(* Logix 5000 project; controller ControlLogix 1756-L63 rev 13.28; software revision 13.03 *)

TASK MainTask (continuous, watchdog 5000 ms) : MainProgram

MODULES
   Local : 1756-L63 (ICP 0, rev 13.28)
      Local_ENBT : 1756-ENBT (Ethernet 105.102.0.155, ICP 3, rev 1.1)
         RemoteENBT_Slot6 : 1756-ENBT (Ethernet 105.102.0.210, rev 1.1, Output RPI 20 ms)
            MNETCR : vendor 1 type 0 code 15 (ICP 1, rev 1.1, Output RPI 5 ms)
END_MODULES

TYPE MNETCRBLOCKSTATS :   // This object is used to store the block transfer statistics for the MVI56-MNETCR module.
STRUCT
   Read : INT;   // Total number of read block transfers
   Write : INT;   // Total number of write block transfers
   Parse : INT;   // Total number of blocks parsed
   Event : INT;   // Total number of event blocks received
   Cmd : INT;   // Total number of command blocks received
   Err : INT;   // Total number of block transfer errors
END_STRUCT
END_TYPE

TYPE MNETCRCLIENTSTATS :   // This object is used to store the port statistics for an MVI56-MNETCR port.
STRUCT
   CmdReq : INT;   // Total number of command list requests sent
   CmdResp : INT;   // Total number of command list responses received
   CmdErr : INT;   // Total number of command list errors
   Requests : INT;   // Total number of requests for port
   Responses : INT;   // Total number of responses for port
   ErrSent : INT;   // Total number of errors sent
   ErrRec : INT;   // Total number of errors received
   CfgErrWord : INT;   // Configuration Error Word
   CurErr : INT;   // Current Error code
   LastErr : INT;   // Last recorded error code
END_STRUCT
END_TYPE

TYPE MNETCRCMDCONTROL :   // MVI56-MNETCR Command Control
STRUCT
   ClientIDreq : INT;   // Requested Client ID.
   CmdQty : INT;   // Command Quantaty for the Client.
   CmdIndex : INT[16];   // Command Index per client. (0 to 15)
END_STRUCT
END_TYPE

TYPE MNETCRCONTROL :   // Values used by program for data transfer operation between the module and the processor.
STRUCT
   BootTimer : TIMER;   // Timer used to clear both cold and warm boot requests
   WarmBoot : BOOL;   // Partial reset of the Module.
   ColdBoot : BOOL;   // Full reset of the Module.
   EventCmdTrigger : BOOL;   // Initiates Event Command.
   EventCmdPending : BOOL;   // Allows Event Command.
   ClientID : INT;   // Client ID to poll a server with the Event Command.
   EventCmd : MNETCREVENTCMD;   // Holds Event Command configuration
   CmdControl : MNETCRCMDCONTROL;   // Holds Command Control status
   CmdControlTrigger : BOOL;   // Initiates Command Control.
   CmdControlPending : BOOL;   // Allows CmdControlTriger.
   IPAddress : MNETCRIPADDRESS;   // IP address statistics including triggers
   WriteCmdBits : INT[30];   // Selects individual clients to to activate its commands.
END_STRUCT
END_TYPE

TYPE MNETCRDATA :   // Contains Read Data (data read from the module to the processor) and Write Data (data written from the processor to the module)
STRUCT
   ReadData : INT[600];   // Data read from module
   WriteData : INT[600];   // Data to write to module
END_STRUCT
END_TYPE

TYPE MNETCREVENTCMD :   // Data structure to use for Event message generation.
STRUCT
   IP0 : INT;   // First digit of IP address
   IP1 : INT;   // Second digit of IP address
   IP2 : INT;   // Third digit of IP address
   IP3 : INT;   // Last digit of IP address
   ServPort : INT;   // TCP Service Port number (0-65535), 502 for MBAP, 2000 for MNET
   SlvAddrNode : INT;   // Modbus slave node address (0 to 247)
   DBAddress : INT;   // Module internal database to use with message
   Count : INT;   // Register or data point count
   Swap : INT;   // Swap code to use with functions 3 and 4
   MBFunction : INT;   // Modbus function code for message
   Address : INT;   // Address to interface with in device
END_STRUCT
END_TYPE

TYPE MNETCRIPADDRESS :   // This object holds IP address status with set IP & get IP triggers.
STRUCT
   IPgetTrigger : BOOL;   // Triggers get IP address.
   IPreceived : INT[4];   // Displays received IP address.
   IPsetTrigger : BOOL;   // Triggers set IP address
   IPrequested : INT[4];   // Displays requested IP address
END_STRUCT
END_TYPE

TYPE MNETCRMODULEDEF :   // This defines the whole module which includes all tags used in the program
STRUCT
   DATA : MNETCRDATA;   // Data read from module
   CONTROL : MNETCRCONTROL;   // Client ,Server Status and blocks status
   STATUS : MNETCRSTATUS;   // MNETCR Module control
   UTIL : MNETCRUTIL;   // Block statistics
END_STRUCT
END_TYPE

TYPE MNETCRSTATUS :   // This status data is returned on each read block and can be used to detect proper module operation.
STRUCT
   PassCnt : INT;   // Program cycle counter
   BlockStats : MNETCRBLOCKSTATS;   // Block Statistics
   CmdBits : INT[30];   // Client Command Status.
   ClientStatsTrigger : BOOL;   // Get Client Status
   ClientIDReq : INT;   // Client ID requested.
   ClientStatus : MNETCRCLIENTSTATS[30];   // Client Status requests
   ClientIDRec : INT;   // Client ID received.
   CmdErrorList : INT[16];   // Cmd Error List
   ClientStatsPending : BOOL;   // Allows Get Client Status
END_STRUCT
END_TYPE

TYPE MNETCRUTIL :   // Values used by program for data transfer operation between the module and the processor.
STRUCT
   LastRead : INT;   // Index of last read block
   LastWrite : INT;   // Index of last write block
   BlockIndex : INT;   // Computed block offset for data table
   ReadDataSizeGet : INT;   // Gets ReadData Array Length.
   WriteDataSizeGet : INT;   // Gets WriteData Array Length.
   ReadDataBlkCount : INT;   // Holds the value of the Block Counts of the Read Data Array.
   WriteDataBlkCount : INT;   // Holds the value of the Block Counts of the Write Data Array.
   RBTSremainder : INT;   // Holds remainder calculation value from the read array.
   WBTSremainder : INT;   // Holds remainder calculation value from the write array.
   IPgetPending : BOOL;   // Allows setting IP
   IPsetPending : BOOL;   // Allowes getting IP
END_STRUCT
END_TYPE

VAR_GLOBAL   (* controller tags *)
   MJFAULTS : DINT[12] := ([0] := 1272054862, [1] := 191551, [3] := 1256603824, [4] := 191551, [9] := 1004);
   MNETCR : MNETCRMODULEDEF;
        .INSTAT.CMDERRORLIST[0]   // Reads Command related errors
        .GETIPADDRESS   // Initiates the retreaval of IP Address from the module.
        .READIPADDRESS.IP[0]   // Reads Module's set IP Address
        .BLK3000CLIENTID   // Holds Block 3000 Client ID
        .CMDCNTRL   // Initiates Command Control
        .HALTCMDCNTRL   // Halts Command Control until the Module is ready for the next Command.
        .HALTEVENTCMD   // Halts Event Initiation until the Module is ready for the next Event.
        .SETIPADDRESS   // Initiates the setting of the IP Address for the module.
        .GETCLNTSTAT   // Initiates retreaval of Client Status.
        .HALTCLNTSTAT   // Halts Client Status Retreaval until the Module is ready for the next Status Retreaval.
        .EVENTCMD   // Initiates an Event.
        .WARMBOOT   // Re-loads MNET.CFG file
        .BLK5000CLIENTID   // Holds Block 5000 Client ID
        .BLK_1CLIENTID   // Holds Client ID for Command Bits Control.
        .HALTCMDBITCNTRL   // Halts Command Control Bits execution until the Module is ready for the next Command.
        .COLDBOOT   // Re-initializes all the module's parameters
        .BLK2000CLIENTID   // Client's Index ID.
        .BP.LASTREAD   // Index of last read block
        .BP.LASTWRITE   // Holds the value to be written on the last scan.
        .HALTSETIPADDRESS   // Halts the IP Adress Setting until the Module is ready for it.
        .HALTGETIPADDR   // Halts the IP Retreaval until the module is ready.
        .WRITEIPADDRESSACK.IP[0]   // Ack. from the module that it has received the new IP Address
END_VAR

PROGRAM MainProgram   (* routine attr 65 MainRoutine *)

ROUTINE MainRoutine   (* ladder *)
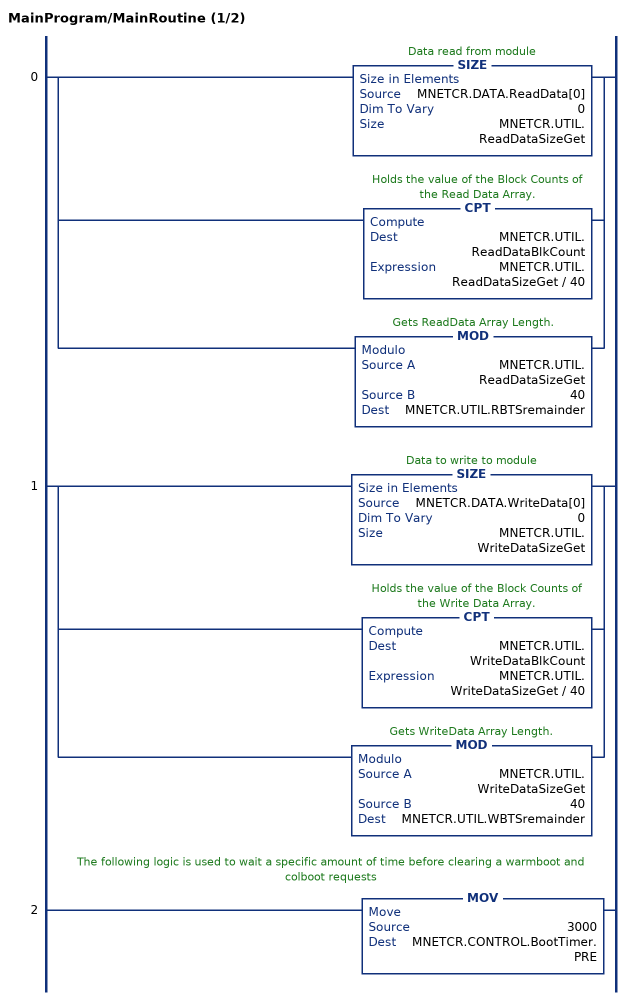
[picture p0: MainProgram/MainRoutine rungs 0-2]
   0: [SIZE(MNETCR.DATA.ReadData[0],0,MNETCR.UTIL.ReadDataSizeGet) ,CPT(MNETCR.UTIL.ReadDataBlkCount,MNETCR.UTIL.ReadDataSizeGet / 40) ,MOD(MNETCR.UTIL.ReadDataSizeGet,40,MNETCR.UTIL.RBTSremainder) ];
   1: [SIZE(MNETCR.DATA.WriteData[0],0,MNETCR.UTIL.WriteDataSizeGet) ,CPT(MNETCR.UTIL.WriteDataBlkCount,MNETCR.UTIL.WriteDataSizeGet / 40) ,MOD(MNETCR.UTIL.WriteDataSizeGet,40,MNETCR.UTIL.WBTSremainder) ];
   // The following logic is used to wait a specific amount of time before clearing a warmboot and colboot requests
   2: MOV(3000,MNETCR.CONTROL.BootTimer.PRE);
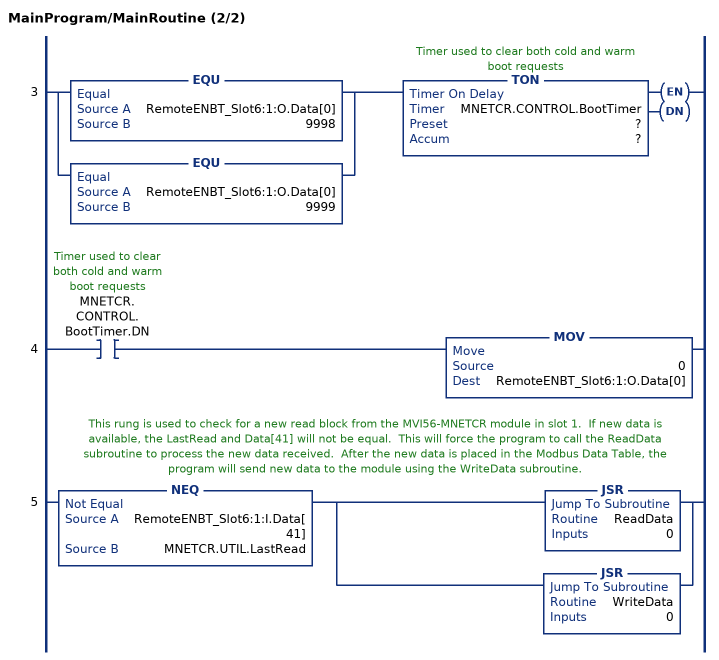
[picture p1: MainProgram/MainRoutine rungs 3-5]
   3: [EQU(RemoteENBT_Slot6:1:O.Data[0],9998) ,EQU(RemoteENBT_Slot6:1:O.Data[0],9999) ]TON(MNETCR.CONTROL.BootTimer,?,?);
   4: XIC(MNETCR.CONTROL.BootTimer.DN)MOV(0,RemoteENBT_Slot6:1:O.Data[0]);
   // This rung is used to check for a new read block from the MVI56-MNETCR module in slot 1.  If new data is available, the LastRead and Data[41] will not be equal.  This will force the program to call the ReadData subroutine to process the new data received.  After the new data is placed in the Modbus Data Table, the program will send new data to the module using the WriteData subroutine.
   5: NEQ(RemoteENBT_Slot6:1:I.Data[41],MNETCR.UTIL.LastRead)[JSR(ReadData,0) ,JSR(WriteData,0) ];
END_ROUTINE

ROUTINE ReadData   (* ladder *)
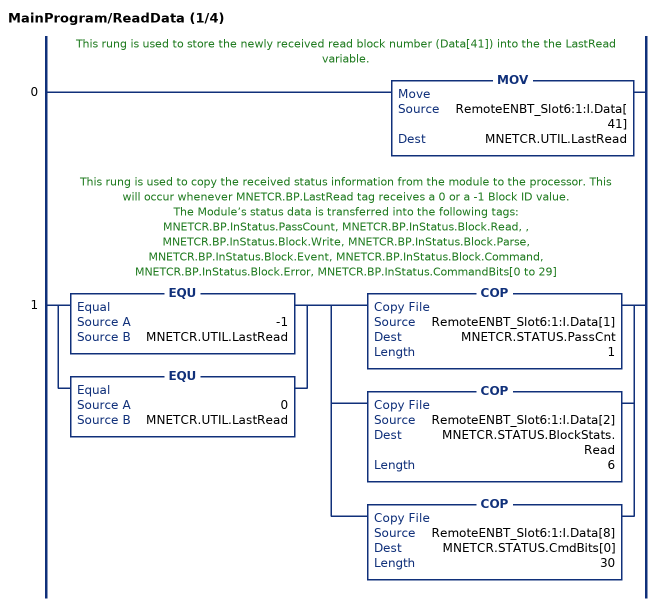
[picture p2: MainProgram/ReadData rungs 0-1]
   // This rung is used to store the newly received read block number (Data[41]) into the the LastRead variable.
   0: MOV(RemoteENBT_Slot6:1:I.Data[41],MNETCR.UTIL.LastRead);
   // This rung is used to copy the received status information from the module to the processor. This will occur whenever MNETCR.BP.LastRead tag receives a 0 or a -1 Block ID value.
   // The Module’s status data is transferred into the following tags:
   // MNETCR.BP.InStatus.PassCount, MNETCR.BP.InStatus.Block.Read, , MNETCR.BP.InStatus.Block.Write, MNETCR.BP.InStatus.Block.Parse, MNETCR.BP.InStatus.Block.Event, MNETCR.BP.InStatus.Block.Command, MNETCR.BP.InStatus.Block.Error, MNETCR.BP.InStatus.CommandBits[0 to 29]
   1: [EQU(-1,MNETCR.UTIL.LastRead) ,EQU(0,MNETCR.UTIL.LastRead) ][COP(RemoteENBT_Slot6:1:I.Data[1],MNETCR.STATUS.PassCnt,1) ,COP(RemoteENBT_Slot6:1:I.Data[2],MNETCR.STATUS.BlockStats.Read,6) ,COP(RemoteENBT_Slot6:1:I.Data[8],MNETCR.STATUS.CmdBits[0],30) ];
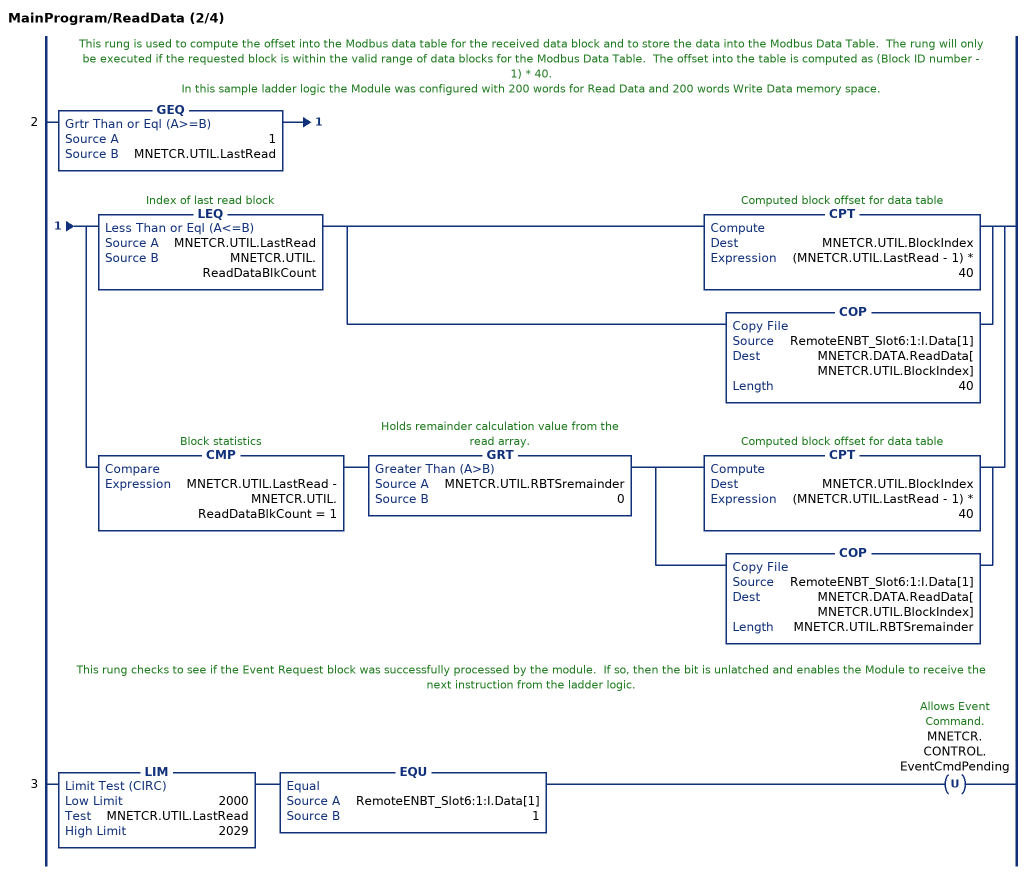
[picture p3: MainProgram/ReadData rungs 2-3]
   // This rung is used to compute the offset into the Modbus data table for the received data block and to store the data into the Modbus Data Table.  The rung will only be executed if the requested block is within the valid range of data blocks for the Modbus Data Table.  The offset into the table is computed as (Block ID number - 1) * 40.
   // In this sample ladder logic the Module was configured with 200 words for Read Data and 200 words Write Data memory space.
   2: GEQ(1,MNETCR.UTIL.LastRead)[LEQ(MNETCR.UTIL.LastRead,MNETCR.UTIL.ReadDataBlkCount) [CPT(MNETCR.UTIL.BlockIndex,(MNETCR.UTIL.LastRead - 1) * 40) ,COP(RemoteENBT_Slot6:1:I.Data[1],MNETCR.DATA.ReadData[MNETCR.UTIL.BlockIndex],40) ] ,CMP(MNETCR.UTIL.LastRead - MNETCR.UTIL.ReadDataBlkCount = 1) GRT(MNETCR.UTIL.RBTSremainder,0) [CPT(MNETCR.UTIL.BlockIndex,(MNETCR.UTIL.LastRead - 1) * 40) ,COP(RemoteENBT_Slot6:1:I.Data[1],MNETCR.DATA.ReadData[MNETCR.UTIL.BlockIndex],MNETCR.UTIL.RBTSremainder) ] ];
   // This rung checks to see if the Event Request block was successfully processed by the module.  If so, then the bit is unlatched and enables the Module to receive the next instruction from the ladder logic.
   3: LIM(2000,MNETCR.UTIL.LastRead,2029)EQU(RemoteENBT_Slot6:1:I.Data[1],1)OTU(MNETCR.CONTROL.EventCmdPending);
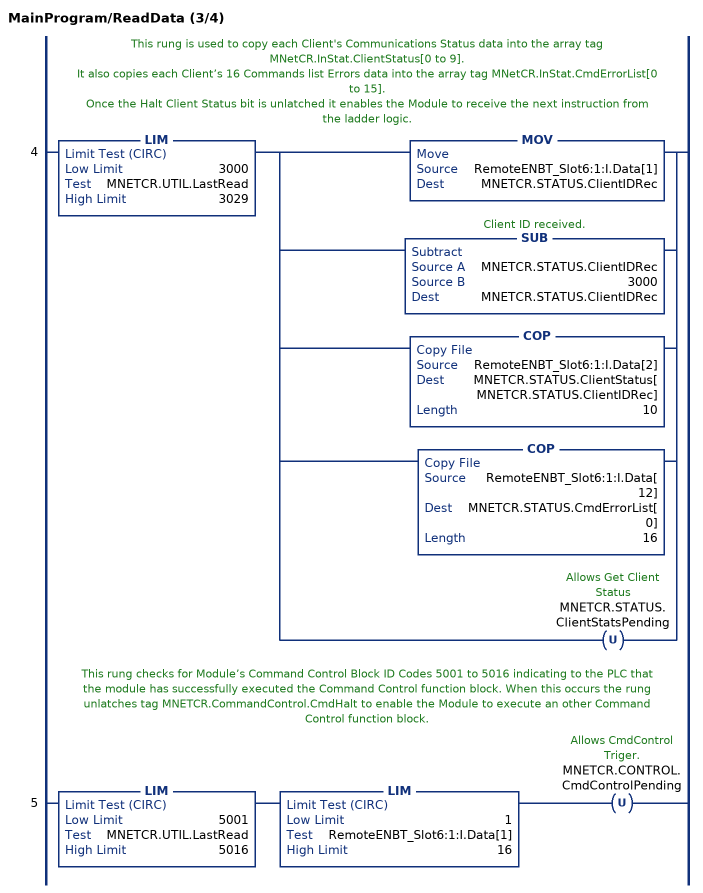
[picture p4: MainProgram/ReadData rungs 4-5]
   // This rung is used to copy each Client's Communications Status data into the array tag MNetCR.InStat.ClientStatus[0 to 9].
   // It also copies each Client’s 16 Commands list Errors data into the array tag MNetCR.InStat.CmdErrorList[0 to 15].
   // Once the Halt Client Status bit is unlatched it enables the Module to receive the next instruction from the ladder logic.
   4: LIM(3000,MNETCR.UTIL.LastRead,3029)[MOV(RemoteENBT_Slot6:1:I.Data[1],MNETCR.STATUS.ClientIDRec) ,SUB(MNETCR.STATUS.ClientIDRec,3000,MNETCR.STATUS.ClientIDRec) ,COP(RemoteENBT_Slot6:1:I.Data[2],MNETCR.STATUS.ClientStatus[MNETCR.STATUS.ClientIDRec],10) ,COP(RemoteENBT_Slot6:1:I.Data[12],MNETCR.STATUS.CmdErrorList[0],16) ,OTU(MNETCR.STATUS.ClientStatsPending) ];
   // This rung checks for Module’s Command Control Block ID Codes 5001 to 5016 indicating to the PLC that the module has successfully executed the Command Control function block. When this occurs the rung unlatches tag MNETCR.CommandControl.CmdHalt to enable the Module to execute an other Command Control function block.
   5: LIM(5001,MNETCR.UTIL.LastRead,5016)LIM(1,RemoteENBT_Slot6:1:I.Data[1],16)OTU(MNETCR.CONTROL.CmdControlPending);
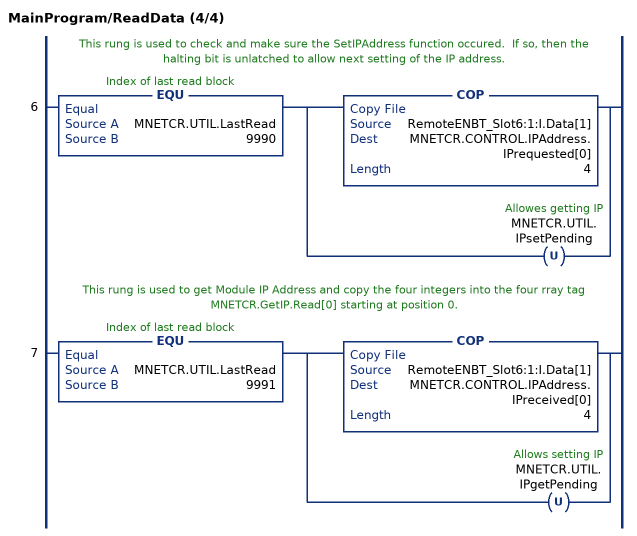
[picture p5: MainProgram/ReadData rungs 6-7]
   // This rung is used to check and make sure the SetIPAddress function occured.  If so, then the halting bit is unlatched to allow next setting of the IP address.
   6: EQU(MNETCR.UTIL.LastRead,9990)[COP(RemoteENBT_Slot6:1:I.Data[1],MNETCR.CONTROL.IPAddress.IPrequested[0],4) ,OTU(MNETCR.UTIL.IPsetPending) ];
   // This rung is used to get Module IP Address and copy the four integers into the four rray tag MNETCR.GetIP.Read[0] starting at position 0.
   7: EQU(MNETCR.UTIL.LastRead,9991)[COP(RemoteENBT_Slot6:1:I.Data[1],MNETCR.CONTROL.IPAddress.IPreceived[0],4) ,OTU(MNETCR.UTIL.IPgetPending) ];
END_ROUTINE

ROUTINE WriteData   (* ladder *)
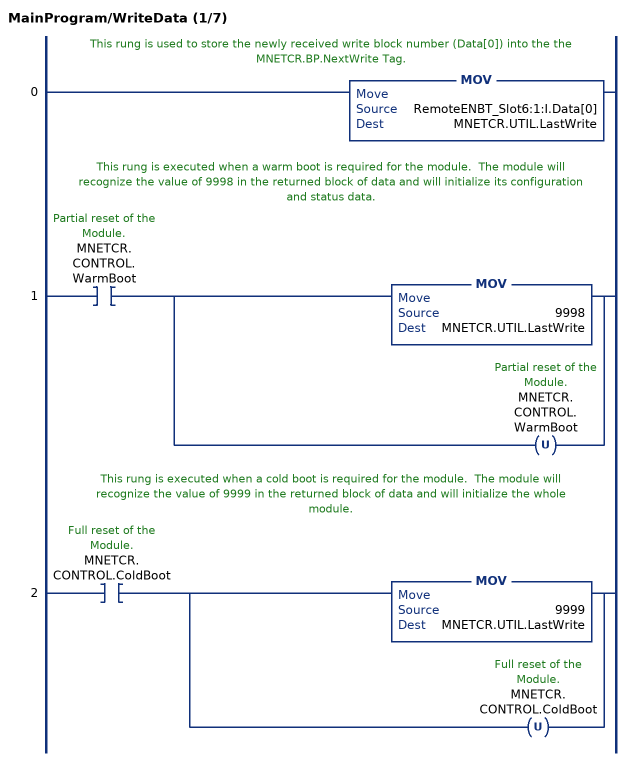
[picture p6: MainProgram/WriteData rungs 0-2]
   // This rung is used to store the newly received write block number (Data[0]) into the the MNETCR.BP.NextWrite Tag.
   0: MOV(RemoteENBT_Slot6:1:I.Data[0],MNETCR.UTIL.LastWrite);
   // This rung is executed when a warm boot is required for the module.  The module will recognize the value of 9998 in the returned block of data and will initialize its configuration and status data.
   1: XIC(MNETCR.CONTROL.WarmBoot)[MOV(9998,MNETCR.UTIL.LastWrite) ,OTU(MNETCR.CONTROL.WarmBoot) ];
   // This rung is executed when a cold boot is required for the module.  The module will recognize the value of 9999 in the returned block of data and will initialize the whole module.
   2: XIC(MNETCR.CONTROL.ColdBoot)[MOV(9999,MNETCR.UTIL.LastWrite) ,OTU(MNETCR.CONTROL.ColdBoot) ];
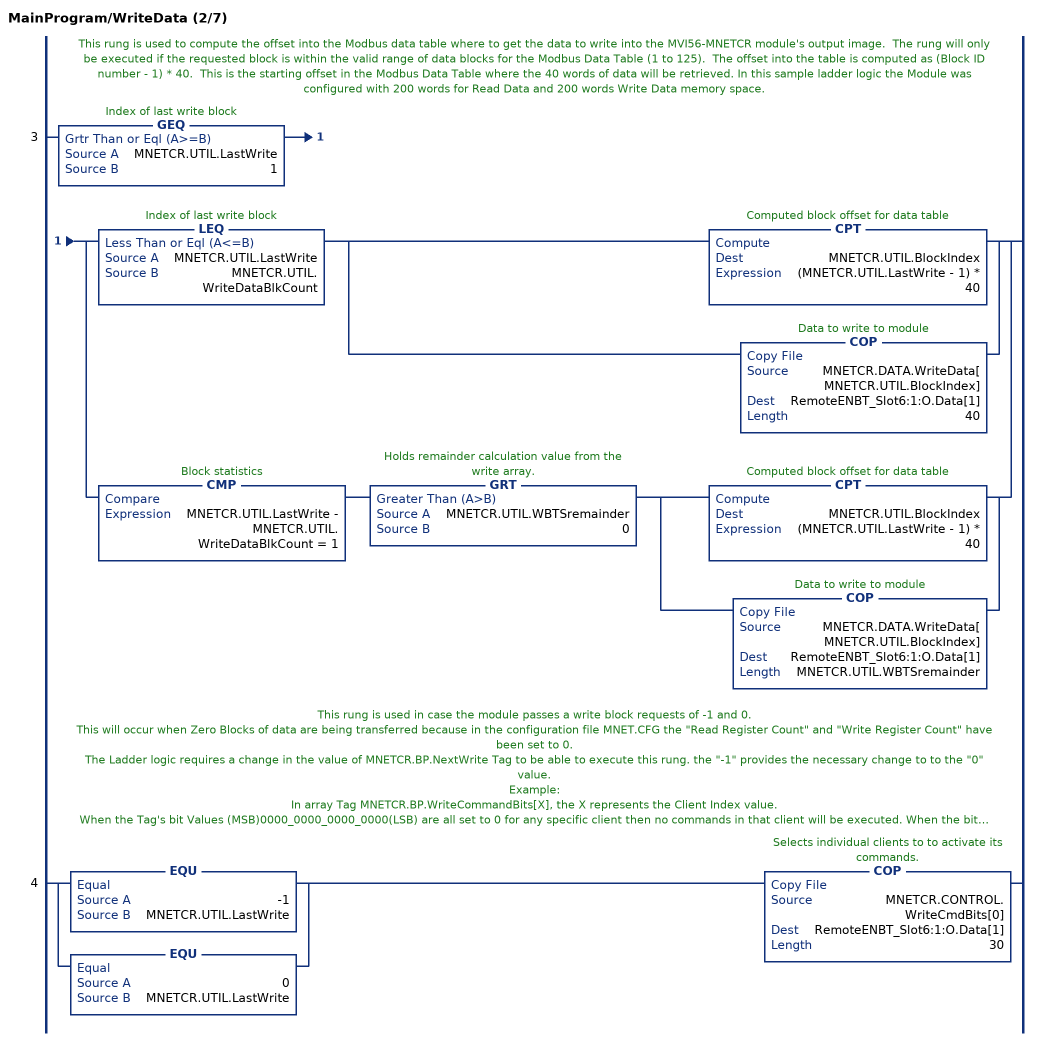
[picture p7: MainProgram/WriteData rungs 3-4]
   // This rung is used to compute the offset into the Modbus data table where to get the data to write into the MVI56-MNETCR module's output image.  The rung will only be executed if the requested block is within the valid range of data blocks for the Modbus Data Table (1 to 125).  The offset into the table is computed as (Block ID number - 1) * 40.  This is the starting offset in the Modbus Data Table where the 40 words of data will be retrieved. In this sample ladder logic the Module was configured with 200 words for Read Data and 200 words Write Data memory space.
   3: GEQ(MNETCR.UTIL.LastWrite,1)[LEQ(MNETCR.UTIL.LastWrite,MNETCR.UTIL.WriteDataBlkCount) [CPT(MNETCR.UTIL.BlockIndex,(MNETCR.UTIL.LastWrite - 1) * 40) ,COP(MNETCR.DATA.WriteData[MNETCR.UTIL.BlockIndex],RemoteENBT_Slot6:1:O.Data[1],40) ] ,CMP(MNETCR.UTIL.LastWrite - MNETCR.UTIL.WriteDataBlkCount = 1) GRT(MNETCR.UTIL.WBTSremainder,0) [CPT(MNETCR.UTIL.BlockIndex,(MNETCR.UTIL.LastWrite - 1) * 40) ,COP(MNETCR.DATA.WriteData[MNETCR.UTIL.BlockIndex],RemoteENBT_Slot6:1:O.Data[1],MNETCR.UTIL.WBTSremainder) ] ];
   // This rung is used in case the module passes a write block requests of -1 and 0.
   // This will occur when Zero Blocks of data are being transferred because in the configuration file MNET.CFG the "Read Register Count" and "Write Register Count" have been set to 0.
   // The Ladder logic requires a change in the value of MNETCR.BP.NextWrite Tag to be able to execute this rung. the "-1" provides the necessary change to to the "0" value.
   // Example:
   // In array Tag MNETCR.BP.WriteCommandBits[X], the X represents the Client Index value.
   // When the Tag's bit Values (MSB)0000_0000_0000_0000(LSB) are all set to 0 for any specific client then no commands in that client will be executed. When the bits are set as follows (MSB)0100_0000_1000_1101(LSB) then 1st,3d, 4th, 8th and 15th command will be executed each time the module generates Block ID of 0.
   4: [EQU(-1,MNETCR.UTIL.LastWrite) ,EQU(0,MNETCR.UTIL.LastWrite) ]COP(MNETCR.CONTROL.WriteCmdBits[0],RemoteENBT_Slot6:1:O.Data[1],30);
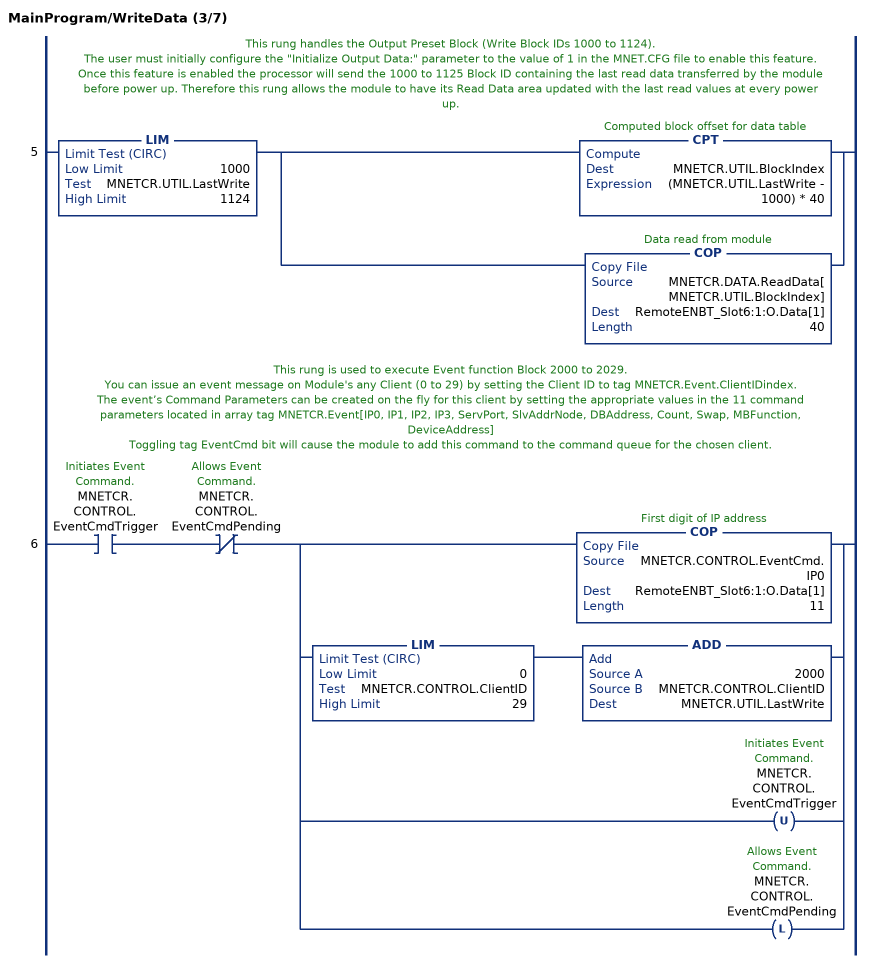
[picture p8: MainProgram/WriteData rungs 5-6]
   // This rung handles the Output Preset Block (Write Block IDs 1000 to 1124).
   // The user must initially configure the "Initialize Output Data:" parameter to the value of 1 in the MNET.CFG file to enable this feature. Once this feature is enabled the processor will send the 1000 to 1125 Block ID containing the last read data transferred by the module before power up. Therefore this rung allows the module to have its Read Data area updated with the last read values at every power up.
   5: LIM(1000,MNETCR.UTIL.LastWrite,1124)[CPT(MNETCR.UTIL.BlockIndex,(MNETCR.UTIL.LastWrite - 1000) * 40) ,COP(MNETCR.DATA.ReadData[MNETCR.UTIL.BlockIndex],RemoteENBT_Slot6:1:O.Data[1],40) ];
   // This rung is used to execute Event function Block 2000 to 2029.
   // You can issue an event message on Module's any Client (0 to 29) by setting the Client ID to tag MNETCR.Event.ClientIDindex.
   // The event’s Command Parameters can be created on the fly for this client by setting the appropriate values in the 11 command parameters located in array tag MNETCR.Event[IP0, IP1, IP2, IP3, ServPort, SlvAddrNode, DBAddress, Count, Swap, MBFunction, DeviceAddress]
   // Toggling tag EventCmd bit will cause the module to add this command to the command queue for the chosen client.
   6: XIC(MNETCR.CONTROL.EventCmdTrigger)XIO(MNETCR.CONTROL.EventCmdPending)[COP(MNETCR.CONTROL.EventCmd.IP0,RemoteENBT_Slot6:1:O.Data[1],11) ,LIM(0,MNETCR.CONTROL.ClientID,29) ADD(2000,MNETCR.CONTROL.ClientID,MNETCR.UTIL.LastWrite) ,OTU(MNETCR.CONTROL.EventCmdTrigger) ,OTL(MNETCR.CONTROL.EventCmdPending) ];
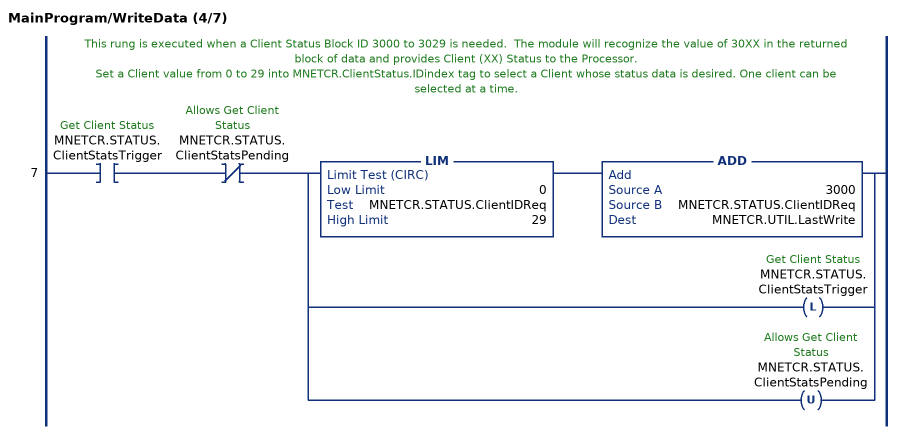
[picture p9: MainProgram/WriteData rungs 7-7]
   // This rung is executed when a Client Status Block ID 3000 to 3029 is needed.  The module will recognize the value of 30XX in the returned block of data and provides Client (XX) Status to the Processor.
   // Set a Client value from 0 to 29 into MNETCR.ClientStatus.IDindex tag to select a Client whose status data is desired. One client can be selected at a time.
   7: XIC(MNETCR.STATUS.ClientStatsTrigger)XIO(MNETCR.STATUS.ClientStatsPending)[LIM(0,MNETCR.STATUS.ClientIDReq,29) ADD(3000,MNETCR.STATUS.ClientIDReq,MNETCR.UTIL.LastWrite) ,OTL(MNETCR.STATUS.ClientStatsTrigger) ,OTU(MNETCR.STATUS.ClientStatsPending) ];
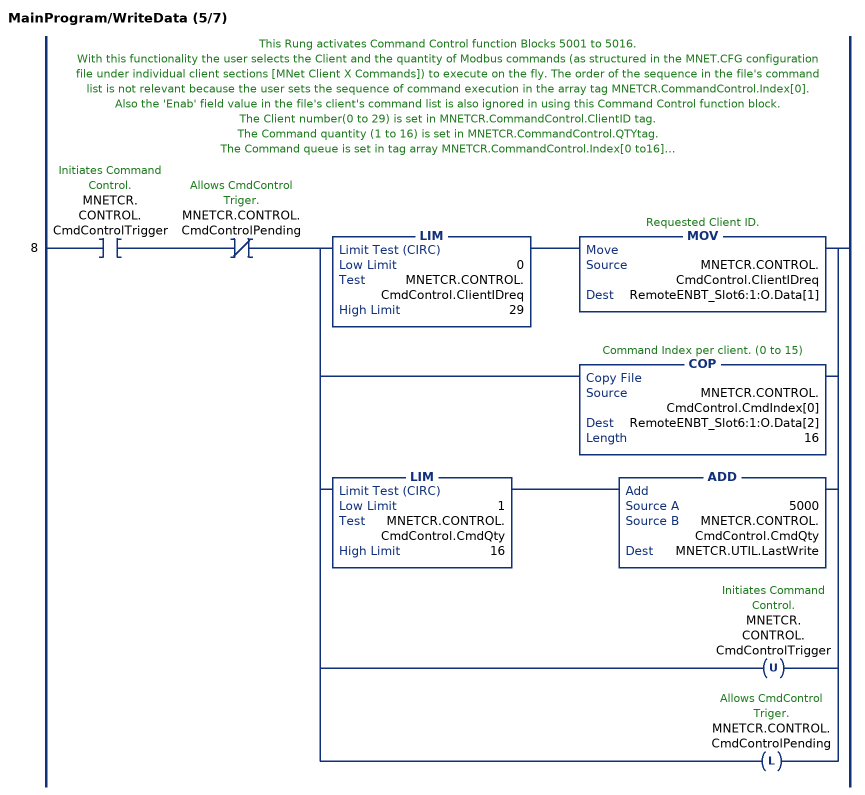
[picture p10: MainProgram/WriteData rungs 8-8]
   // This Rung activates Command Control function Blocks 5001 to 5016.
   // With this functionality the user selects the Client and the quantity of Modbus commands (as structured in the MNET.CFG configuration file under individual client sections [MNet Client X Commands]) to execute on the fly. The order of the sequence in the file's command list is not relevant because the user sets the sequence of command execution in the array tag MNETCR.CommandControl.Index[0]. Also the 'Enab' field value in the file's client's command list is also ignored in using this Command Control function block.
   // The Client number(0 to 29) is set in MNETCR.CommandControl.ClientID tag.
   // The Command quantity (1 to 16) is set in MNETCR.CommandControl.QTYtag.
   // The Command queue is set in tag array MNETCR.CommandControl.Index[0 to16].
   // Example:
   // To have Client 12 request Modbus Commands indexed from 4 to 6 (total 3) in the following order; 5, 4, 6set the tags as follows:
   // MNETCR.CommandControl.ClientID = 12
   // MNETCR.CommandControl.QTY = 3
   // MNETCR.CommandControl.Index [0] = 5
   // MNETCR.CommandControl.Index [1] = 4
   // MNETCR.CommandControl.Index [2] = 6
   // Command ID 5 will be executed first followed by command 4 then followed by command 6.
   8: XIC(MNETCR.CONTROL.CmdControlTrigger)XIO(MNETCR.CONTROL.CmdControlPending)[LIM(0,MNETCR.CONTROL.CmdControl.ClientIDreq,29) MOV(MNETCR.CONTROL.CmdControl.ClientIDreq,RemoteENBT_Slot6:1:O.Data[1]) ,COP(MNETCR.CONTROL.CmdControl.CmdIndex[0],RemoteENBT_Slot6:1:O.Data[2],16) ,LIM(1,MNETCR.CONTROL.CmdControl.CmdQty,16) ADD(5000,MNETCR.CONTROL.CmdControl.CmdQty,MNETCR.UTIL.LastWrite) ,OTU(MNETCR.CONTROL.CmdControlTrigger) ,OTL(MNETCR.CONTROL.CmdControlPending) ];
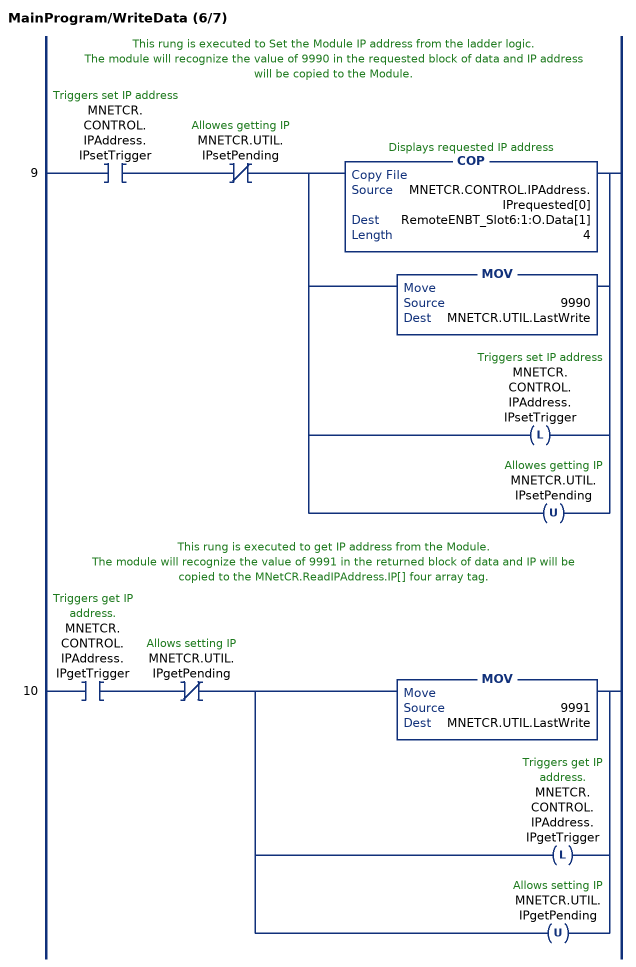
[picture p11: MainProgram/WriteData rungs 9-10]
   // This rung is executed to Set the Module IP address from the ladder logic.
   //  The module will recognize the value of 9990 in the requested block of data and IP address will be copied to the Module.
   9: XIC(MNETCR.CONTROL.IPAddress.IPsetTrigger)XIO(MNETCR.UTIL.IPsetPending)[COP(MNETCR.CONTROL.IPAddress.IPrequested[0],RemoteENBT_Slot6:1:O.Data[1],4) ,MOV(9990,MNETCR.UTIL.LastWrite) ,OTL(MNETCR.CONTROL.IPAddress.IPsetTrigger) ,OTU(MNETCR.UTIL.IPsetPending) ];
   // This rung is executed to get IP address from the Module.
   //  The module will recognize the value of 9991 in the returned block of data and IP will be copied to the MNetCR.ReadIPAddress.IP[] four array tag.
   10: XIC(MNETCR.CONTROL.IPAddress.IPgetTrigger)XIO(MNETCR.UTIL.IPgetPending)[MOV(9991,MNETCR.UTIL.LastWrite) ,OTL(MNETCR.CONTROL.IPAddress.IPgetTrigger) ,OTU(MNETCR.UTIL.IPgetPending) ];
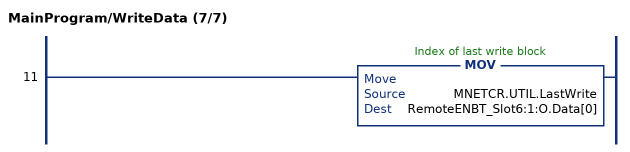
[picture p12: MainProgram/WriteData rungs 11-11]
   11: MOV(MNETCR.UTIL.LastWrite,RemoteENBT_Slot6:1:O.Data[0]);
END_ROUTINE
END_PROGRAM

PROGRAM StartUp   (* routine attr 65 PowerUp *)

ROUTINE PowerUp   (* ladder *)
// This routine is executed each time the module is powered up or restarted.
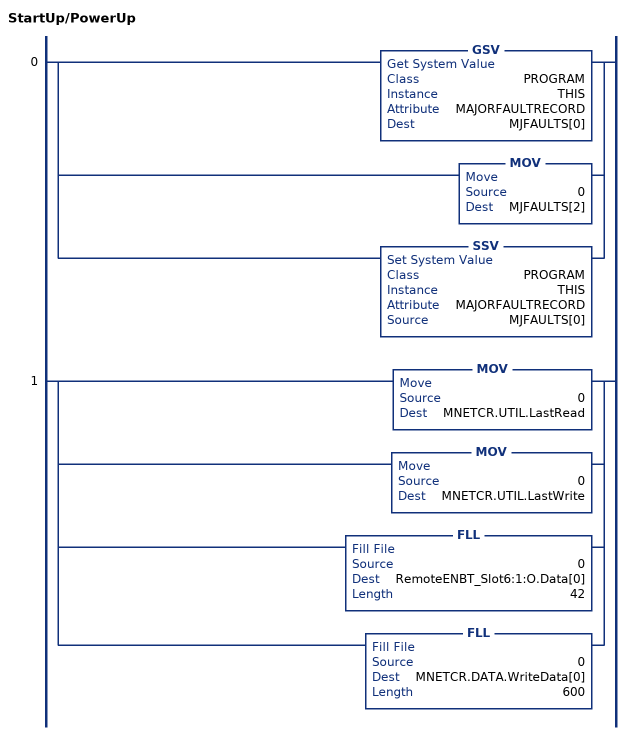
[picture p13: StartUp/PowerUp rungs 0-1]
   0: [GSV(PROGRAM,THIS,MAJORFAULTRECORD,MJFAULTS[0]) ,MOV(0,MJFAULTS[2]) ,SSV(PROGRAM,THIS,MAJORFAULTRECORD,MJFAULTS[0]) ];
   1: [MOV(0,MNETCR.UTIL.LastRead) ,MOV(0,MNETCR.UTIL.LastWrite) ,FLL(0,RemoteENBT_Slot6:1:O.Data[0],42) ,FLL(0,MNETCR.DATA.WriteData[0],600) ];
END_ROUTINE
END_PROGRAM
